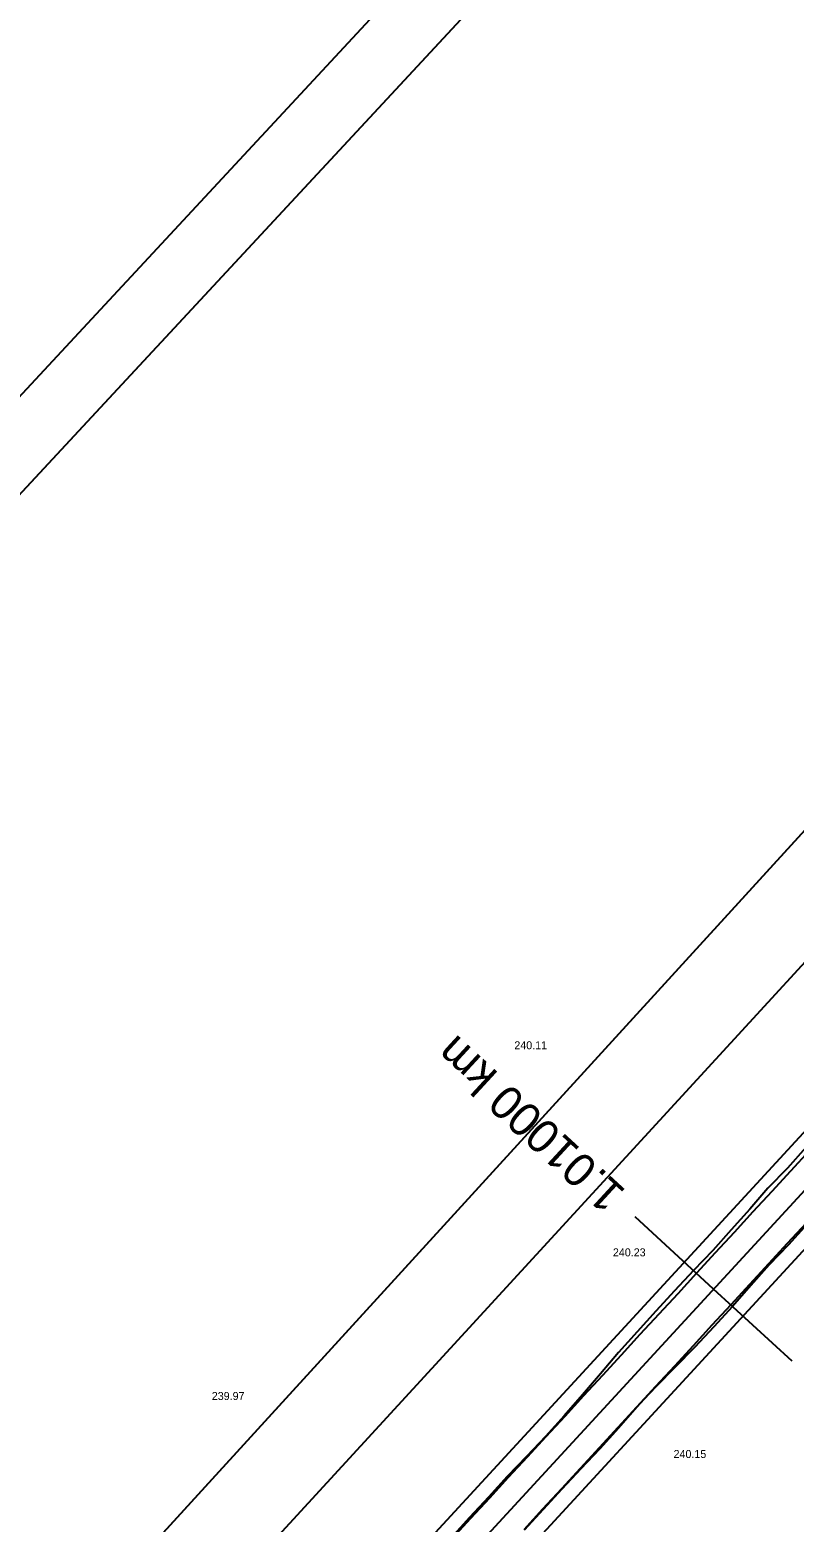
# Model space of a CAD drawing. Extents: x -555887 to -552101, y -1100251 to -1096546.
# Drawn here: x -555592.8 to -555535.5, y -1098323 to -1098211.1 of the extents above; entities that cross this region are included whole.
import ezdxf

# ---------------------------------------------------------------- set-up
doc = ezdxf.new("R2010")
doc.units = 0
for name, color, linetype in [('IP_návrh', 7, 'Continuous'), ('PARCELY_cesty', 7, 'Continuous'), ('POLYGONY_SITUACE_PF', 7, 'Continuous'), ('POLYGONY_SITUACE_PF_POPISY', 7, 'Continuous'), ('POLYGONY_SITUACE_PO', 7, 'Continuous'), ('ram_VC1', 7, 'Continuous'), ('Výškopis', 7, 'Continuous'), ('zájem', 7, 'Continuous')]:
    doc.layers.add(name, color=color, linetype=linetype)

msp = doc.modelspace()

# ---------------------------------------------------------------- linework, layer by layer
at = {"layer": 'IP_návrh'}
msp.add_lwpolyline([(-555730.85, -1098494.64), (-555471.29, -1098211.98), (-555447.19, -1098191.79), (-555406.99, -1098193.78), (-555291.32, -1098130.27), (-555281.27, -1098119.66), (-555272.34, -1098101.41), (-555266.18, -1098052.11), (-555246.83, -1098023.92), (-555193.03, -1097978.41), (-554985.79, -1097744.7), (-554956.17, -1097701), (-554939.23, -1097656.04), (-554918.86, -1097601.97), (-554899.16, -1097585.1)], dxfattribs=at)
at = {"layer": 'PARCELY_cesty'}
for points in [[(-555292.25, -1098142.16), (-555364.66, -1098183.69), (-555371.39, -1098184.89), (-555389.15, -1098194.9), (-555393.3, -1098199.76), (-555401.17, -1098203.38), (-555408.61, -1098205.15), (-555413.73, -1098205.81), (-555419.9, -1098205.25), (-555424.4, -1098204.19), (-555432.4, -1098202.4), (-555443.11, -1098202.67), (-555453.18, -1098206.29), (-555457.86, -1098209.4), (-555461.71, -1098212.96), (-555470.07, -1098223.51), (-555661.76, -1098431.65)], [(-555289.09, -1098147.26), (-555393.06, -1098207.11), (-555398.23, -1098209.64), (-555403.79, -1098211.47), (-555409.56, -1098212.52), (-555415.41, -1098212.79), (-555421.27, -1098212.25), (-555428.99, -1098211.34), (-555433.17, -1098210.42), (-555441.62, -1098210.63), (-555449.56, -1098213.49), (-555452.96, -1098215.75), (-555460.12, -1098221.55), (-555719.84, -1098503.56)]]:
    msp.add_lwpolyline(points, dxfattribs=at)
at = {"layer": 'POLYGONY_SITUACE_PF'}
for p, q in [((-555541.53, -1098305.52), (-555547.41, -1098300.1)), ((-555535.64, -1098310.94), (-555541.53, -1098305.52))]:
    msp.add_line(p, q, dxfattribs=at)
at = {"layer": 'POLYGONY_SITUACE_PO'}
for p, q in [((-555458.91, -1098215.81), (-555722.13, -1098501.62)), ((-555534.6, -1098294.91), (-555535.99, -1098296.46)), ((-555534.34, -1098295.14), (-555535.76, -1098296.68)), ((-555535.99, -1098296.46), (-555537.45, -1098297.95)), ((-555535.76, -1098296.68), (-555537.17, -1098298.21)), ((-555537.45, -1098297.95), (-555538.81, -1098299.53)), ((-555537.17, -1098298.21), (-555538.58, -1098299.74)), ((-555538.81, -1098299.53), (-555540.2, -1098301.08)), ((-555538.58, -1098299.74), (-555539.99, -1098301.27)), ((-555540.2, -1098301.08), (-555541.59, -1098302.63)), ((-555539.99, -1098301.27), (-555541.4, -1098302.81)), ((-555534.59, -1098300.58), (-555536, -1098302.11)), ((-555534.59, -1098300.58), (-555536, -1098302.11)), ((-555534.51, -1098300.65), (-555535.9, -1098302.21)), ((-555536, -1098302.11), (-555537.42, -1098303.64)), ((-555536, -1098302.11), (-555537.42, -1098303.64)), ((-555535.9, -1098302.21), (-555537.35, -1098303.7)), ((-555541.59, -1098302.63), (-555543.03, -1098304.14)), ((-555541.4, -1098302.81), (-555542.81, -1098304.34)), ((-555537.42, -1098303.64), (-555538.83, -1098305.18)), ((-555537.42, -1098303.64), (-555538.83, -1098305.18)), ((-555537.35, -1098303.7), (-555538.74, -1098305.25)), ((-555543.03, -1098304.14), (-555544.47, -1098305.65)), ((-555542.81, -1098304.34), (-555544.22, -1098305.87)), ((-555544.47, -1098305.65), (-555545.87, -1098307.19)), ((-555544.22, -1098305.87), (-555545.64, -1098307.4)), ((-555538.83, -1098305.18), (-555540.24, -1098306.71)), ((-555538.83, -1098305.18), (-555540.24, -1098306.71)), ((-555538.74, -1098305.25), (-555540.12, -1098306.82)), ((-555540.24, -1098306.71), (-555541.65, -1098308.24)), ((-555540.24, -1098306.71), (-555541.65, -1098308.24)), ((-555540.12, -1098306.82), (-555541.52, -1098308.36)), ((-555545.87, -1098307.19), (-555547.26, -1098308.74)), ((-555545.64, -1098307.4), (-555547.05, -1098308.94)), ((-555547.26, -1098308.74), (-555548.67, -1098310.28)), ((-555547.05, -1098308.94), (-555548.46, -1098310.47)), ((-555541.65, -1098308.24), (-555543.06, -1098309.77)), ((-555541.65, -1098308.24), (-555543.06, -1098309.77)), ((-555541.52, -1098308.36), (-555542.93, -1098309.89)), ((-555548.67, -1098310.28), (-555550.01, -1098311.87)), ((-555543.06, -1098309.77), (-555544.47, -1098311.31)), ((-555543.06, -1098309.77), (-555544.47, -1098311.31)), ((-555542.93, -1098309.89), (-555544.4, -1098311.38)), ((-555548.46, -1098310.47), (-555549.87, -1098312)), ((-555544.47, -1098311.31), (-555545.88, -1098312.84)), ((-555544.47, -1098311.31), (-555545.88, -1098312.84)), ((-555544.4, -1098311.38), (-555545.86, -1098312.86)), ((-555550.01, -1098311.87), (-555551.37, -1098313.46)), ((-555549.87, -1098312), (-555551.28, -1098313.53)), ((-555551.37, -1098313.46), (-555552.74, -1098315.02)), ((-555551.28, -1098313.53), (-555552.69, -1098315.07)), ((-555545.88, -1098312.84), (-555547.3, -1098314.37)), ((-555545.88, -1098312.84), (-555547.3, -1098314.37)), ((-555546.77, -1098313.81), (-555547.28, -1098314.39)), ((-555545.86, -1098312.86), (-555546.77, -1098313.81)), ((-555547.3, -1098314.37), (-555548.71, -1098315.9)), ((-555547.3, -1098314.37), (-555548.71, -1098315.9)), ((-555547.28, -1098314.39), (-555548.65, -1098315.95)), ((-555552.74, -1098315.02), (-555554.13, -1098316.57)), ((-555552.69, -1098315.07), (-555554.1, -1098316.6)), ((-555548.71, -1098315.9), (-555550.12, -1098317.44)), ((-555548.71, -1098315.9), (-555550.12, -1098317.44)), ((-555548.65, -1098315.95), (-555550.05, -1098317.5)), ((-555554.13, -1098316.57), (-555555.57, -1098318.08)), ((-555554.1, -1098316.6), (-555555.52, -1098318.13)), ((-555555.57, -1098318.08), (-555557, -1098319.59)), ((-555555.52, -1098318.13), (-555556.93, -1098319.66)), ((-555550.12, -1098317.44), (-555551.53, -1098318.97)), ((-555550.12, -1098317.44), (-555551.53, -1098318.97)), ((-555550.05, -1098317.5), (-555551.49, -1098319.01)), ((-555551.53, -1098318.97), (-555552.94, -1098320.5)), ((-555551.53, -1098318.97), (-555552.94, -1098320.5)), ((-555551.49, -1098319.01), (-555552.91, -1098320.53)), ((-555557, -1098319.59), (-555558.42, -1098321.12)), ((-555556.93, -1098319.66), (-555558.34, -1098321.2)), ((-555552.94, -1098320.5), (-555554.35, -1098322.03)), ((-555552.94, -1098320.5), (-555554.35, -1098322.03)), ((-555558.42, -1098321.12), (-555559.83, -1098322.66)), ((-555558.34, -1098321.2), (-555559.75, -1098322.73)), ((-555552.91, -1098320.53), (-555554.32, -1098322.06)), ((-555559.83, -1098322.66), (-555561.23, -1098324.19)), ((-555559.75, -1098322.73), (-555561.16, -1098324.26)), ((-555554.35, -1098322.03), (-555555.76, -1098323.57)), ((-555554.35, -1098322.03), (-555555.76, -1098323.57)), ((-555554.32, -1098322.06), (-555555.73, -1098323.6))]:
    msp.add_line(p, q, dxfattribs=at)
at = {"layer": 'ram_VC1'}
for points in [[(-554540.88, -1097849.11), (-554911.62, -1097504.63), (-555880.62, -1098547.51), (-555509.88, -1098891.98)], [(-554547.95, -1097849.37), (-554911.36, -1097511.7), (-555873.55, -1098547.25), (-555510.14, -1098884.91)]]:
    msp.add_lwpolyline(points, close=True, dxfattribs=at)
for points in [[(-554540.88, -1097849.11), (-554911.62, -1097504.63), (-555880.62, -1098547.51), (-555509.88, -1098891.98), (-554540.88, -1097849.11)], [(-555510.14, -1098884.91), (-555873.55, -1098547.25), (-554911.36, -1097511.7), (-554547.95, -1097849.37), (-555510.14, -1098884.91)]]:
    msp.add_lwpolyline(points, dxfattribs=at)
at = {"layer": 'zájem'}
for points in [[(-555238.64, -1097948.52), (-555252.57, -1097963.73), (-555279.76, -1097993.33), (-555293.44, -1098008.21), (-555307.4, -1098023.39), (-555319.27, -1098036.32), (-555345.7, -1098065.12), (-555359.04, -1098079.61), (-555372.52, -1098094.26), (-555387.16, -1098110.21), (-555420.24, -1098146.3), (-555426.79, -1098153.42), (-555433.69, -1098160.92), (-555440.91, -1098168.86), (-555445.23, -1098173.52), (-555448.48, -1098177.05), (-555451.73, -1098180.59), (-555493.09, -1098225.57), (-555626.26, -1098371.34)], [(-555626.26, -1098371.34), (-555493.09, -1098225.57), (-555451.73, -1098180.59), (-555448.48, -1098177.05), (-555445.23, -1098173.52), (-555440.91, -1098168.86), (-555433.69, -1098160.92), (-555426.79, -1098153.42), (-555420.24, -1098146.3), (-555387.16, -1098110.21), (-555372.52, -1098094.26), (-555359.04, -1098079.61), (-555345.7, -1098065.12), (-555319.27, -1098036.32), (-555307.4, -1098023.39), (-555293.44, -1098008.21), (-555279.76, -1097993.33), (-555252.57, -1097963.73), (-555238.64, -1097948.52)]]:
    msp.add_lwpolyline(points, dxfattribs=at)

# ---------------------------------------------------------------- texts
at = {"layer": 'POLYGONY_SITUACE_PF_POPISY'}
msp.add_text('1.01000 km', height=2.5, rotation=137.3558, dxfattribs=at).set_placement((-555548.02, -1098298.18))
at = {"layer": 'Výškopis'}
for s, p in [('240.11', (-555556.47, -1098287.54)), ('240.23', (-555549.08, -1098303.07)), ('239.97', (-555579.16, -1098313.84)), ('240.15', (-555544.53, -1098318.19))]:
    msp.add_text(s, height=0.6, dxfattribs=at).set_placement(p)

doc.saveas('drawing.dxf')
